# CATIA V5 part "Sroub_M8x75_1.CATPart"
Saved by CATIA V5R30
Part number: Sroub_M8x75_1
Definition: E 1200_8x75_2
Nomenclature: E 1200_8x75_2
Source: Unknown
Description: PART--DESC
Bounding box of the stored display mesh (mm): x -136 to -123, y 12.01 to 24.99, z 11.2 to 94.2
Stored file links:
  E:\Bakalarka\Model\Forma_v7\Sroub_M8x75_1.CATPart
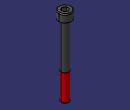
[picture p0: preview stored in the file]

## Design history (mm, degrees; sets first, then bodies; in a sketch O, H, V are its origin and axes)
Body1 "MANIFOLD_SOLID_BREP #3618" (main body)
  Solid1: solid without history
